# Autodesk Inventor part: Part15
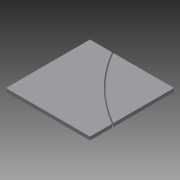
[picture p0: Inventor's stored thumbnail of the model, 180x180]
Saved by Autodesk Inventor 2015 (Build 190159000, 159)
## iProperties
Created: 2015-04
Part Number: Part15
Material: Generic
Document SubType Name: Modeling
Designer: TREINA5
Density: 1 g/cm^3
Appearance: Default
Mass: 129555 g
Surface Area: 48565.4 cm^2
Volume: 129555 cm^3
Author: TREINA5
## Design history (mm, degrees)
sketch "Sketch1"
  geometry: L1 (10898.159, 7499.198)-(11979.983, 7499.198); L2 (10500, 7499.198)-(10874.958, 7499.198); L3 (10500, 7479.198)-(10886.462, 7479.198); L4 (10909.766, 7479.198)-(11979.983, 7479.198); L5 (10500, 6000)-(10500, 7480); L6 (11979.983, 5999.198)-(10499.983, 5999.198); L7 (11979.983, 5999.198)-(10499.983, 5999.198); L8 (11979.983, 5999.198)-(11979.983, 6386.041); L9 (12000, 6374.536)-(12000, 5999.198); L10 (10499.983, 7479.198)-(10499.983, 5999.198); L11 (10499.983, 7479.198)-(10499.983, 5999.198); L12 (13149.912, 5999.198)-(11999.983, 5999.198); L13 (13149.912, 5999.198)-(11999.983, 5999.198); L14 (11979.983, 6409.341)-(11979.983, 7479.198); L15 (12000, 7479.198)-(12000, 6397.733); L16 (13479.814, 7479.198)-(13479.998, 6000.083); L17 (12000, 7479.198)-(13479.814, 7479.198); L18 (11940.002, 8980)-(11979.983, 8980); L19 (11979.983, 7499.198)-(11979.983, 8980); L20 (10701.515, 8980)-(11940.002, 8980); L21 (10500, 8980)-(10740.282, 8980); L22 (10500, 8642.5)-(10500, 7499.198); L23 (11979.983, 5999.198)-(10499.983, 5999.198); L24 (10499.983, 5999.198)-(10499.983, 7479.198); L25 (11979.983, 7479.198)-(11979.983, 6409.341); L26 (11979.983, 6386.041)-(11979.983, 5999.198); L27 (10499.983, 7479.198)-(10886.462, 7479.198); L28 (10909.766, 7479.198)-(11979.983, 7479.198); A1 r 3010.067 centre (13489.917, 8990) between (10886.462, 7479.198) and (11979.983, 6386.041); A2 r 2989.933 centre (13489.917, 8990) between (10909.766, 7479.198) and (11979.983, 6409.341); A3 r 3010.067 centre (13489.917, 8990) between (12000, 6374.536) and (13149.912, 5999.198); A4 r 2989.933 centre (13489.917, 8990) between (12000, 6397.733) and (13479.998, 6000.083); A5 r 2989.933 centre (13489.917, 8990) between (10500, 8980) and (10898.159, 7499.198); A6 r 3010.067 centre (13489.917, 8990) between (10500, 8642.293) and (10874.958, 7499.198); A7 r 3010.067 centre (13489.917, 8990) between (10886.462, 7479.198) and (11979.983, 6386.041); A8 r 3010.067 centre (13489.917, 8990) between (13149.912, 5999.198) and (10500, 8642.293); 1 further point
  constraints: 57 end point, 17 point on circle, 8 centre point, 6 point on line, 4 parallel, 4 perpendicular, 2 horizontal
extrude "Extrusion1" new body sketch "Sketch1" distance "d0" = 60; taper "d1" = 0 deg
extrude "Extrusion2" new body sketch "Sketch1" distance "d2" = 60; taper "d3" = 0 deg
body "Solid1"
body "Solid2"
